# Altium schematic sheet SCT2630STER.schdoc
size 127 x 101 mm
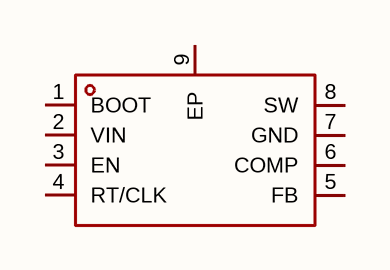
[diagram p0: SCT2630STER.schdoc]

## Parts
U?  sct2630ster  [ESOP-8_L4.9-W3.9-P1.27-LS6.0-BL-EP-2]  (value not drawn)

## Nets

Not connected (* = marked no-connect by the designer): U? 1(BOOT) 2(VIN) 3(EN) 4(RT/CLK) 5(FB) 6(COMP) 7(GND) 8(SW) 9(EP)

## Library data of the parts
U? = sct2630ster: 功能类型:降压型;工作电压:4.5V~60V;输出电压:800mV~57V;输出电流:3A;输出类型:可调;; Manufacturer: SCT(芯洲科技); AddInBom: yes; ModelId: 0078439d9e964752ad4b3f828dcb5664; ModelTransform: 192.913,236.22,0,0,0,0,0,0,0; Function: 降压型; Output Current: 3A; Frequency - Switching: 100kHz~1.2MHz；500kHz; Synchronous Rectifier: 否; Number of Outputs: 1; Topology: 降压式; Quiescent Current: 190uA; Switch tube (built-in/external): 内置; Output Type: 可调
